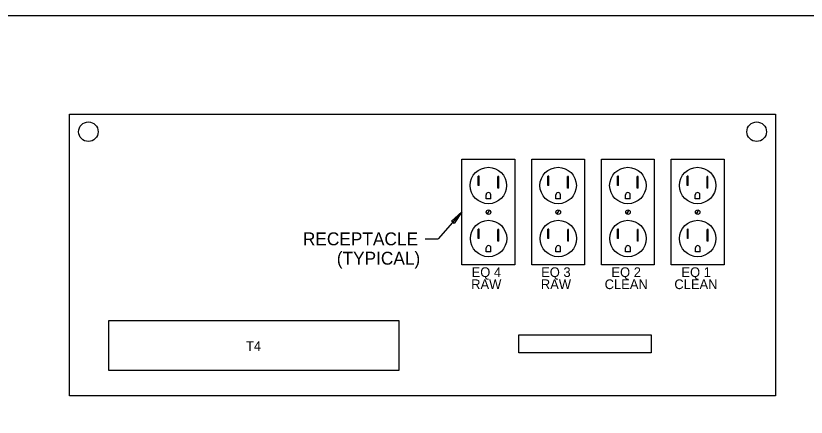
# Model space of a CAD drawing. Extents: x 99862 to 103680, y 99470 to 102076.
# Drawn here: x 100936 to 101916, y 101578 to 102076 of the extents above; entities that cross this region are included whole.
import ezdxf

# ---------------------------------------------------------------- set-up
doc = ezdxf.new("R2010")
doc.units = 0
for name, color, linetype in [('Level 1', 7, 'Continuous'), ('Level 11', 7, 'Continuous'), ('Level 15', 7, 'Continuous'), ('Level 20', 7, 'Continuous'), ('Level 26', 7, 'Continuous'), ('Level 40', 7, 'Continuous')]:
    doc.layers.add(name, color=color, linetype=linetype)

msp = doc.modelspace()

# ---------------------------------------------------------------- linework, layer by layer
at = {"layer": 'Level 1'}
msp.add_lwpolyline([(99862, 99999.5), (103151, 99999.5), (103151, 102075.5), (99862, 102075.5)], close=True, dxfattribs=at)
at = {"layer": 'Level 11'}
for p, q in [((101509.55, 101865.09), (101509.55, 101876.47)), ((101510.7, 101876.47), (101509.55, 101876.47)), ((101510.7, 101865.09), (101510.7, 101876.47)), ((101534.03, 101861.77), (101534.03, 101876.43)), ((101535.14, 101876.43), (101534.03, 101876.43)), ((101535.14, 101861.77), (101535.14, 101876.43)), ((101595.97, 101865.09), (101595.97, 101876.47)), ((101597.12, 101876.47), (101595.97, 101876.47)), ((101597.12, 101865.09), (101597.12, 101876.47)), ((101620.46, 101861.77), (101620.46, 101876.43)), ((101621.57, 101876.43), (101620.46, 101876.43)), ((101621.57, 101861.77), (101621.57, 101876.43)), ((101682.4, 101865.09), (101682.4, 101876.47)), ((101683.55, 101876.47), (101682.4, 101876.47)), ((101683.55, 101865.09), (101683.55, 101876.47)), ((101706.89, 101861.77), (101706.89, 101876.43)), ((101707.99, 101876.43), (101706.89, 101876.43)), ((101707.99, 101861.77), (101707.99, 101876.43)), ((101768.83, 101865.09), (101768.83, 101876.47)), ((101769.98, 101876.47), (101768.83, 101876.47)), ((101769.98, 101865.09), (101769.98, 101876.47)), ((101793.32, 101861.77), (101793.32, 101876.43)), ((101794.42, 101876.43), (101793.32, 101876.43)), ((101794.42, 101861.77), (101794.42, 101876.43)), ((101510.7, 101865.09), (101509.55, 101865.09)), ((101597.12, 101865.09), (101595.97, 101865.09)), ((101683.55, 101865.09), (101682.4, 101865.09)), ((101769.98, 101865.09), (101768.83, 101865.09)), ((101535.14, 101861.77), (101534.03, 101861.77)), ((101621.57, 101861.77), (101620.46, 101861.77)), ((101707.99, 101861.77), (101706.89, 101861.77)), ((101794.42, 101861.77), (101793.32, 101861.77)), ((101519.43, 101848.74), (101519.43, 101853.51)), ((101525.26, 101848.74), (101519.43, 101848.74)), ((101525.26, 101848.74), (101525.26, 101853.47)), ((101605.86, 101848.74), (101605.86, 101853.51)), ((101611.68, 101848.74), (101605.86, 101848.74)), ((101611.68, 101848.74), (101611.68, 101853.47)), ((101692.28, 101848.74), (101692.28, 101853.51)), ((101698.11, 101848.74), (101692.28, 101848.74)), ((101698.11, 101848.74), (101698.11, 101853.47)), ((101778.71, 101848.74), (101778.71, 101853.51)), ((101784.54, 101848.74), (101778.71, 101848.74)), ((101784.54, 101848.74), (101784.54, 101853.47)), ((101509.68, 101799.35), (101509.68, 101810.78)), ((101510.81, 101810.78), (101509.68, 101810.78)), ((101510.81, 101799.35), (101510.81, 101810.78)), ((101534.15, 101796.05), (101534.15, 101810.69)), ((101535.3, 101810.69), (101534.15, 101810.69)), ((101535.3, 101796.05), (101535.3, 101810.69)), ((101596.11, 101799.35), (101596.11, 101810.78)), ((101597.24, 101810.78), (101596.11, 101810.78)), ((101597.24, 101799.35), (101597.24, 101810.78)), ((101620.57, 101796.05), (101620.57, 101810.69)), ((101621.73, 101810.69), (101620.57, 101810.69)), ((101621.73, 101796.05), (101621.73, 101810.69)), ((101682.54, 101799.35), (101682.54, 101810.78)), ((101683.67, 101810.78), (101682.54, 101810.78)), ((101683.67, 101799.35), (101683.67, 101810.78)), ((101707, 101796.05), (101707, 101810.69)), ((101708.16, 101810.69), (101707, 101810.69)), ((101708.16, 101796.05), (101708.16, 101810.69)), ((101768.96, 101799.35), (101768.96, 101810.78)), ((101770.09, 101810.78), (101768.96, 101810.78)), ((101770.09, 101799.35), (101770.09, 101810.78)), ((101793.43, 101796.05), (101793.43, 101810.69)), ((101794.58, 101810.69), (101793.43, 101810.69)), ((101794.58, 101796.05), (101794.58, 101810.69)), ((101510.81, 101799.35), (101509.68, 101799.35)), ((101597.24, 101799.35), (101596.11, 101799.35)), ((101683.67, 101799.35), (101682.54, 101799.35)), ((101770.09, 101799.35), (101768.96, 101799.35)), ((101519.59, 101783.02), (101519.59, 101787.58)), ((101525.4, 101783.02), (101525.4, 101787.78)), ((101535.3, 101796.05), (101534.15, 101796.05)), ((101606.02, 101783.02), (101606.02, 101787.58)), ((101611.83, 101783.02), (101611.83, 101787.78)), ((101621.73, 101796.05), (101620.57, 101796.05)), ((101692.45, 101783.02), (101692.45, 101787.58)), ((101698.25, 101783.02), (101698.25, 101787.78)), ((101708.16, 101796.05), (101707, 101796.05)), ((101778.87, 101783.02), (101778.87, 101787.58)), ((101784.68, 101783.02), (101784.68, 101787.78)), ((101794.58, 101796.05), (101793.43, 101796.05)), ((101525.4, 101783.02), (101519.59, 101783.02)), ((101611.83, 101783.02), (101606.02, 101783.02)), ((101698.25, 101783.02), (101692.45, 101783.02)), ((101784.68, 101783.02), (101778.87, 101783.02))]:
    msp.add_line(p, q, dxfattribs=at)
for centre in [(101522.31, 101865.06), (101608.74, 101865.06), (101695.17, 101865.06), (101781.6, 101865.06), (101522.46, 101799.33), (101608.88, 101799.33), (101695.31, 101799.33), (101781.74, 101799.33)]:
    msp.add_circle(centre, 22.58, dxfattribs=at)
for centre, radius, start, end in [((101522.33, 101853.45), 2.9, 0.64737, 178.85087), ((101608.75, 101853.45), 2.9, 0.64737, 178.85087), ((101695.18, 101853.45), 2.9, 0.64737, 178.85087), ((101781.61, 101853.45), 2.9, 0.64737, 178.85087), ((101522.49, 101787.6), 2.91, 3.54193, 180.2938), ((101608.92, 101787.6), 2.91, 3.54193, 180.2938), ((101695.35, 101787.6), 2.91, 3.54193, 180.2938), ((101781.78, 101787.6), 2.91, 3.54193, 180.2938)]:
    msp.add_arc(centre, radius, start, end, dxfattribs=at)
at = {"layer": 'Level 15'}
for p in [(101489.52, 101832.23), (101444.04, 101798.91)]:
    msp.add_line(p, (101460.04, 101798.91), dxfattribs=at)
msp.add_lwpolyline([(101489.52, 101832.23), (101479.84, 101817.91), (101478.69, 101819.99), (101476.48, 101820.88)], close=True, dxfattribs=at)
at = {"layer": 'Level 26'}
for points in [[(101003.1, 101953.37), (101878.1, 101953.37), (101878.1, 101604.37), (101003.1, 101604.37)], [(101051.79, 101697.79), (101411.12, 101697.79), (101411.12, 101635.48), (101051.79, 101635.48)], [(101559.88, 101680.08), (101724.14, 101680.08), (101724.14, 101657.7), (101559.88, 101657.7)]]:
    msp.add_lwpolyline(points, close=True, dxfattribs=at)
for centre in [(101026.32, 101931.77), (101854.88, 101931.77)]:
    msp.add_circle(centre, 12.13, dxfattribs=at)
at = {"layer": 'Level 40'}
for p, q in [((101520.99, 101830.03), (101523.39, 101834.21)), ((101521.3, 101829.99), (101523.61, 101833.95)), ((101607.42, 101830.03), (101609.81, 101834.21)), ((101607.73, 101829.99), (101610.04, 101833.95)), ((101693.85, 101830.03), (101696.24, 101834.21)), ((101694.16, 101829.99), (101696.46, 101833.95)), ((101780.27, 101830.03), (101782.67, 101834.21)), ((101780.59, 101829.99), (101782.89, 101833.95))]:
    msp.add_line(p, q, dxfattribs=at)
for points in [[(101555.1, 101897.8), (101555.1, 101766.67), (101489.52, 101766.67), (101489.52, 101897.8)], [(101641.53, 101897.8), (101641.53, 101766.67), (101575.95, 101766.67), (101575.95, 101897.8)], [(101727.96, 101897.8), (101727.96, 101766.67), (101662.38, 101766.67), (101662.38, 101897.8)], [(101814.38, 101897.8), (101814.38, 101766.67), (101748.81, 101766.67), (101748.81, 101897.8)]]:
    msp.add_lwpolyline(points, close=True, dxfattribs=at)
for centre in [(101522.46, 101831.97), (101608.88, 101831.97), (101695.31, 101831.97), (101781.74, 101831.97)]:
    msp.add_circle(centre, 2.84, dxfattribs=at)

# ---------------------------------------------------------------- texts
at = {"layer": 'Level 20'}
for s, height, p in [('RECEPTACLE', 16, (101292.33, 101790.91)), ('(TYPICAL)', 16, (101334.3, 101766.91)), ('EQ 4', 12, (101501.46, 101751.61)), ('EQ 3', 12, (101587.66, 101751.61)), ('EQ 2', 12, (101674.8, 101751.61)), ('EQ 1', 12, (101761.57, 101751.61)), ('RAW', 12, (101500.89, 101736.61)), ('RAW', 12, (101587.32, 101736.61)), ('CLEAN', 12, (101666.42, 101736.61)), ('CLEAN', 12, (101752.84, 101736.61)), ('T4', 12, (101221.75, 101660.05))]:
    msp.add_text(s, height=height, dxfattribs=at).set_placement(p)

doc.saveas('drawing.dxf')
